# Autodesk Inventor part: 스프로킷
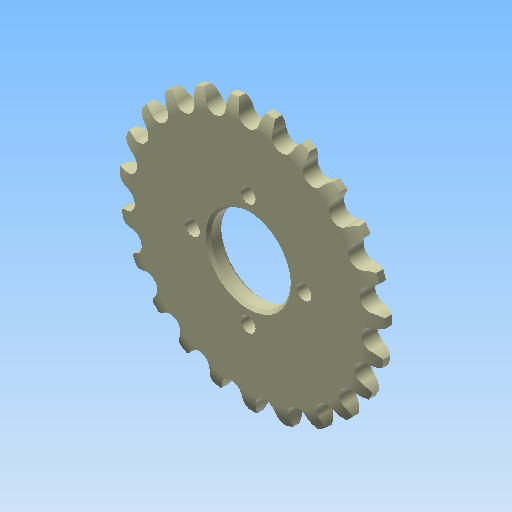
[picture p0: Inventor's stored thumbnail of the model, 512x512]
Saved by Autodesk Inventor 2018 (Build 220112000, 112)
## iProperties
Created: 2024-02
Part Number: 스프로킷
Material: 강철, 합금
Document SubType Name: Modeling
Designer: mdu-01
Density: 1 g/cm^3
Appearance: 기본값(1)
Author: mdu-01
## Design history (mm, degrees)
sketch "스케치1"
  geometry: L1 (0, 2.9)-(0, -2.9); L2 (16, 2.9)-(43.6, 2.9); L3 (50, 1.287)-(50, -1.287); L4 (43.6, -2.9)-(16, -2.9); L5 (15, -1.9)-(15, 1.9); L6 (15, 0)-(50, 0); L7 (16, 2.9)-(15, 1.9); L8 (16, -2.9)-(15, -1.9); A1 r 13.5 centre (43.6, -10.6) between (50, 1.287) and (43.6, 2.9); A2 r 13.5 centre (43.6, 10.6) between (43.6, -2.9) and (50, -1.287); 4 further points
  constraints: 16 end point, 6 point on line, 4 point on circle, 3 midpoint, 3 symmetric about line, 2 centre point, 2 parallel, 1 coincident, 1 horizontal, 1 perpendicular, 1 tangent, 1 vertical, 1 other
  dimensions: "d0" = 5.8 distance of L1.start L1.end; "d2" = 100 diameter of L3 L1; "d3" = 30 diameter of L5 L1; "d4" = 6.4 distance from line of A1.centre L3; "d5" = 13.5 radius of A1; "d8" = 1 distance of point (15, 2.9) L5.end; "d9" = 1 distance of L2.start point (15, 2.9); "d10" = 1 distance of L4.end point (15, -2.9)
revolve "회전1" sketch "스케치1" stored, may be unused: angle "d11" = 90 deg
sketch "스케치2"
  geometry: A1 r 46.635 centre (0, 0) between (0, 46.635) and (12.582, 44.906); A2 r 3.885 centre (0, 46.635) between (-3.849, 46.106) and (3.849, 46.106); A3 r 12.7 centre (0, 46.635) between (12.582, 44.906) and (-12.582, 44.906); A4 r 8.815 centre (12.582, 44.906) between (17.817, 51.998) and (3.849, 46.106); A5 r 8.815 centre (-12.582, 44.906) between (-17.817, 51.998) and (-3.849, 46.106); A6 r 30 centre (0, 27.862) between (17.817, 51.998) and (-17.817, 51.998); 1 further point
  constraints: 13 point on circle, 6 centre point, 4 tangent, 2 coincident, 1 vertical alignment
  dimensions: "d12" = 93.27 diameter of A1; "d13" = 7.77 diameter of A2; "d14" = 25.4 diameter of A3; "d15" = 30 radius of A6
extrude "돌출1" cut sketch "스케치2" extent not by distance; stored distance "d16" = 10; taper "d17" = 0 deg
sketch "스케치3" dims "d21" = 42
  geometry: 3 further points
  constraints: 2 vertical alignment, 1 coincident, 2 other
hole "구멍1" sketch "스케치3" at (0, -25.635) diameter "d22" = 5.5; stored, may be unused: countersink angle "d26" = 90 deg, drill point angle "d28" = 118 deg; dims "d23" = 6, "d24" = 9.4, "d25" = 2, "d27" = 8
node "솔리드1"
pattern_circular "원형 패턴1" dims angle "d19" = 360 deg
pattern_circular "원형 패턴2" dims angle "d30" = 360 deg
